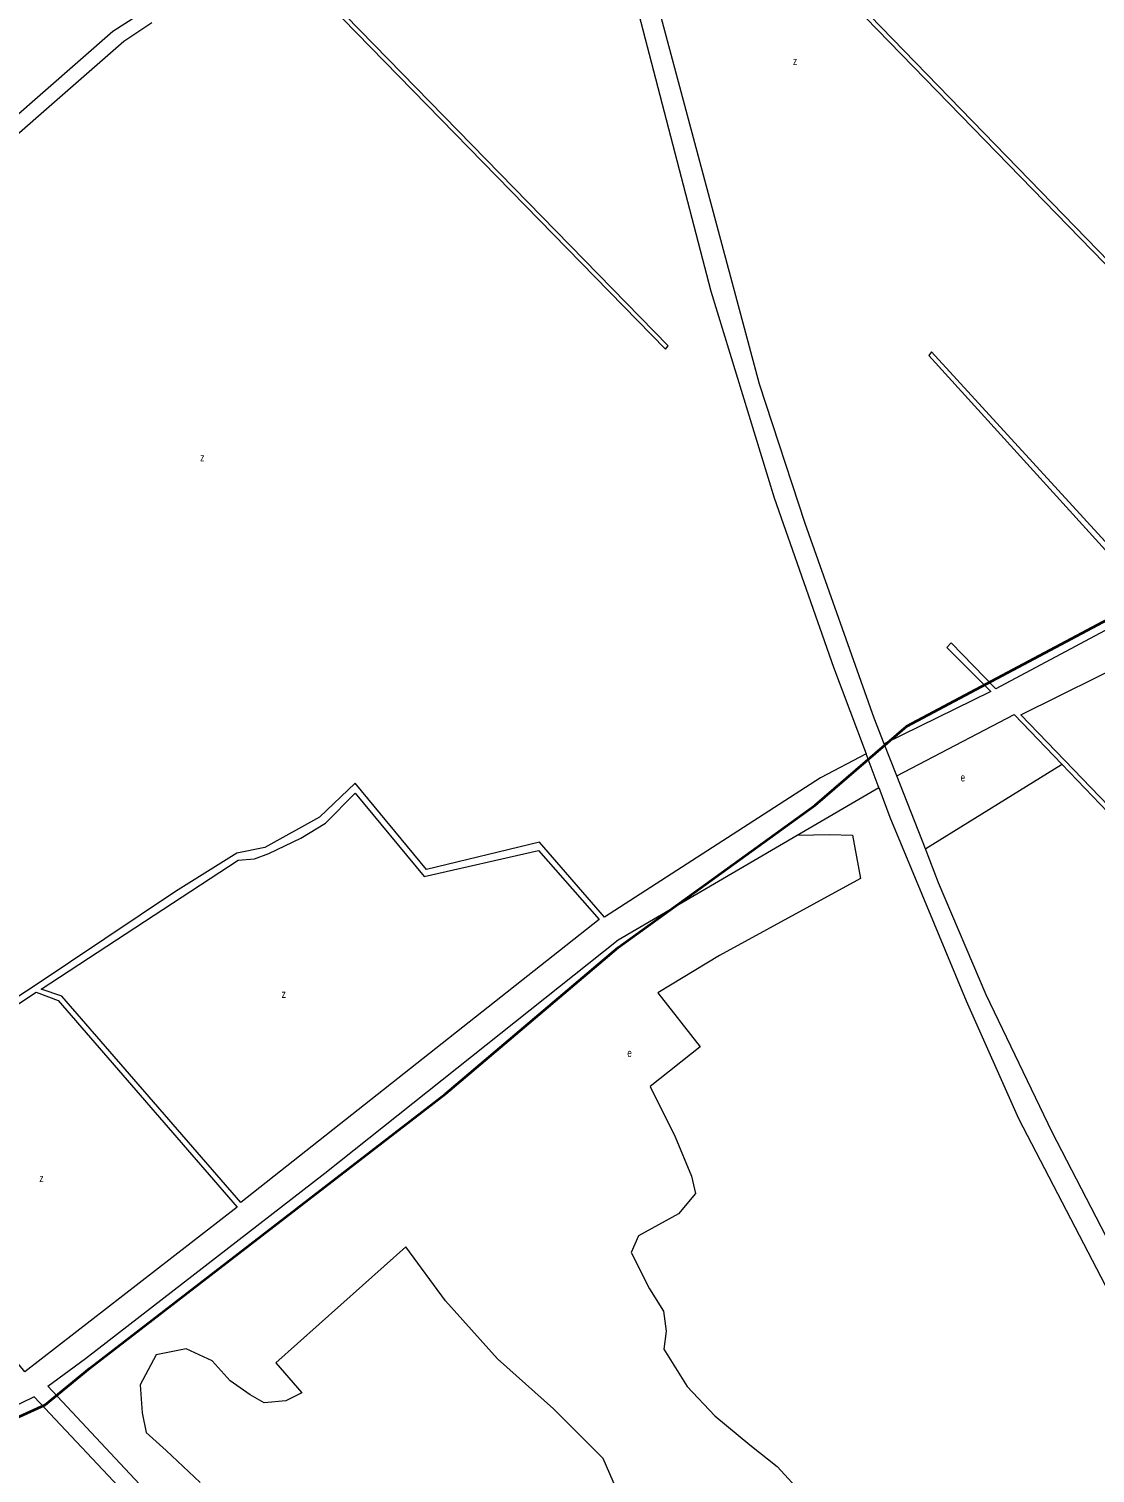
# Model space of a CAD drawing. Extents: x 639657 to 671642, y 222838 to 252123.
# Drawn here: x 657284 to 658616, y 228600 to 230405 of the extents above; entities that cross this region are included whole.
import ezdxf

# ---------------------------------------------------------------- set-up
doc = ezdxf.new("R2010")
doc.units = 0
doc.header["$LTSCALE"] = 4
for name, color, linetype, lineweight in [('1', 7, 'Continuous', 13), ('21', 7, 'Continuous', 13), ('57', 7, 'Continuous', 35)]:
    doc.layers.add(name, color=color, linetype=linetype, lineweight=lineweight)
doc.layers.add('7', color=7, linetype='Continuous')

msp = doc.modelspace()

# ---------------------------------------------------------------- linework, layer by layer
at = {"layer": '1'}
for points in [[(656713.006, 231072.175), (656690.32, 231055.59), (656656.04, 231046.06), (656645.94, 231046.4), (656621.85, 231048.99), (656588.33, 231049.99), (656562.8, 231046.55), (656475.94, 230977.58), (656456.79, 230970.95), (656453.1, 230965.47), (656721.14, 230687.77), (657000.35, 230395.98), (657134.77, 230258.17), (657208.41, 230321.35), (657226.66, 230322.21), (657235.15, 230318.12), (657261.23, 230289.95), (657389.09, 230402.13), (657419.13, 230421.32), (657433.542, 230433.621)], [(658259.327, 230876.683), (658195.37, 230943.05), (658190.81, 230937.54), (658593.22, 230517.59), (658626.79, 230490.5), (658697.43, 230416.21), (658755.22, 230349.33), (659095.77, 229999.44), (659158.63, 229932.35), (658994.94, 229844.55), (658933.48, 229805.77), (658049.87, 230715.95), (658046.21, 230710.93), (658925.75, 229806.65), (658696.94, 229690.25), (658412, 230001.64), (658408.7, 229996.97), (658690.5, 229685.96), (658492.58, 229580.51), (658436.45, 229637.99), (658431.31, 229632.13), (658486.15, 229576.99), (658352.967, 229511.499)], [(658352.967, 229511.499), (658340.37, 229543.69), (658254.12, 229787.05), (658196.99, 229961.22), (657982.63, 230762.26)], [(657570.58, 230526.37), (658079.47, 230004.91), (658082.96, 230008.95), (657574.8, 230529.7)], [(658027.43, 230495.57), (658136.46, 230077.28), (658215.54, 229819.07), (658289.68, 229607.51), (658330.274, 229499.199)], [(657175.31, 230190.97), (657402.74, 230389.56), (657437.82, 230413.18)], [(658368.519, 229471.759), (658515.25, 229548.41), (658575.044, 229485.997)], [(658330.274, 229499.199), (658273.17, 229469.22), (658003.42, 229295.04), (657922.11, 229388.86), (657781.11, 229354.46), (657691.91, 229462.45), (657647.36, 229419.83), (657579.2, 229382.04), (657544.19, 229375.07), (657467.55, 229327.11), (657290.69, 229208.91), (657129.811, 229104.099)], [(658346.127, 229456.903), (658345.377, 229458.903), (658330.274, 229499.199)], [(658368.519, 229471.759), (658367.736, 229473.759), (658352.967, 229511.499)], [(658575.044, 229485.997), (658967.51, 229076.34), (658983.81, 229069.2), (659580.88, 228450.43), (659420.78, 228290.22)], [(658947.715, 228282.75), (658562.78, 229026.3), (658480.4, 229197.86), (658420.89, 229337.93), (658404.328, 229380.253), (658368.519, 229471.759)], [(657712.199, 228334.257), (657681.55, 228309.42), (657307.89, 228709.02), (657355.03, 228743.21), (657653.97, 228974.97), (658020.63, 229266.59), (658244.147, 229397.277), (658346.127, 229456.903)], [(658346.127, 229456.903), (658360.04, 229419.78), (658455.44, 229190.39), (658520.85, 229043.52), (658839.749, 228429.598)]]:
    msp.add_lwpolyline(points, dxfattribs=at)
for points in [[(659511.43, 229210.601), (659298.07, 229095.5), (659202.8, 229191.42), (659195.49, 229186.71), (659290.11, 229089.93), (659078.44, 228978.87), (658994.75, 229067.45), (659006.4, 229091.93), (659080.77, 229136.89), (659077.56, 229142.06), (659004.27, 229097.1), (658991.54, 229072.62), (658972.68, 229081.48), (658523.62, 229547.96), (658668.01, 229619.58), (658949.28, 229773.48), (658962.36, 229770.86)], [(657996.65, 229291.83), (657549.09, 228938.4), (657325.32, 229196.25), (657299.37, 229205.16), (657545.66, 229366.26), (657566.06, 229367.69), (657584.11, 229374.5), (657624.1, 229393.48), (657654.85, 229412.29), (657691.88, 229449.77), (657778.29, 229345.66), (657920.91, 229378.06)], [(657544.35, 228932.4), (657279.18, 228726.76), (657254.37, 228757.15), (657218.9, 228812.94), (657141.67, 228899.2), (657078.32, 228962.84), (657052.46, 229002.05), (657047.86, 229039.23), (657293.34, 229201.1), (657320.58, 229190.68)], [(657173.5, 228259.54), (657383.64, 228029.86), (657666.69, 228295.51), (657290.89, 228695.56), (657091.08, 228598.43), (657299.51, 228373.92)]]:
    msp.add_lwpolyline(points, close=True, dxfattribs=at)
at = {"layer": '21'}
for points in [[(658404.328, 229380.253), (658404.828, 229380.563), (658574.544, 229485.687), (658575.044, 229485.997)], [(658244.147, 229397.277), (658244.647, 229397.29), (658284.375, 229398.323), (658313.141, 229397.404), (658323.167, 229343.4), (658147.005, 229247.206), (658070.182, 229200.503), (658123.163, 229133.048), (658060.57, 229083.472), (658091.922, 229020.611), (658112.221, 228971.13), (658116.973, 228949.81), (658095.786, 228924.289), (658045.819, 228896.56), (658036.901, 228875.841), (658059.496, 228830.331), (658077.325, 228802.732), (658080.351, 228777.439), (658077.692, 228755), (658106.549, 228708.34), (658141.43, 228671.61), (658184.859, 228635.428), (658219.211, 228608.359), (658252.102, 228572.486)], [(658026.862, 228560.886), (658001.924, 228618.277), (657939.579, 228680.659), (657869.752, 228743.042), (657804.913, 228815.405), (657755.036, 228882.778), (657592.938, 228738.051), (657625.358, 228700.622), (657605.407, 228690.641), (657577.975, 228688.145), (657560.519, 228698.126), (657535.58, 228715.593), (657513.136, 228740.546), (657480.716, 228755.518), (657443.309, 228748.032), (657423.359, 228710.603), (657425.853, 228675.669), (657430.84, 228650.716), (657455.778, 228628.258), (657498.173, 228588.334)]]:
    msp.add_lwpolyline(points, dxfattribs=at)
at = {"layer": '57'}
msp.add_lwpolyline([(655815.565, 228539.351), (655868.882, 228465.687), (655932.353, 228381.862), (655965.359, 228351.38), (656059.297, 228308.198), (656122.769, 228310.738), (656247.173, 228333.599), (656539.144, 228394.563), (656541.682, 228397.103), (656737.176, 228452.986), (656945.363, 228513.95), (657128.162, 228605.395), (657304.613, 228685.41), (657360.468, 228731.133), (657804.771, 229074.053), (658020.575, 229256.944), (658266.845, 229434.755), (658381.095, 229533.82), (658640.059, 229670.989), (659364.907, 230043.12), (659418.477, 230072.598)], dxfattribs=at)

# ---------------------------------------------------------------- texts
at = {"layer": '7'}
for s, width, p in [('z', 0.8, (658238.951, 230359.929)), ('z', 0.8, (657498.263, 229864.545)), ('e', 0.75, (658448.496, 229464.531)), ('z', 0.8, (657600.036, 229194.085)), ('e', 0.75, (658032.028, 229120.182)), ('z', 0.8, (657297.317, 228963.93))]:
    msp.add_text(s, height=10, dxfattribs=dict(at, width=width)).set_placement(p)

doc.saveas('drawing.dxf')
